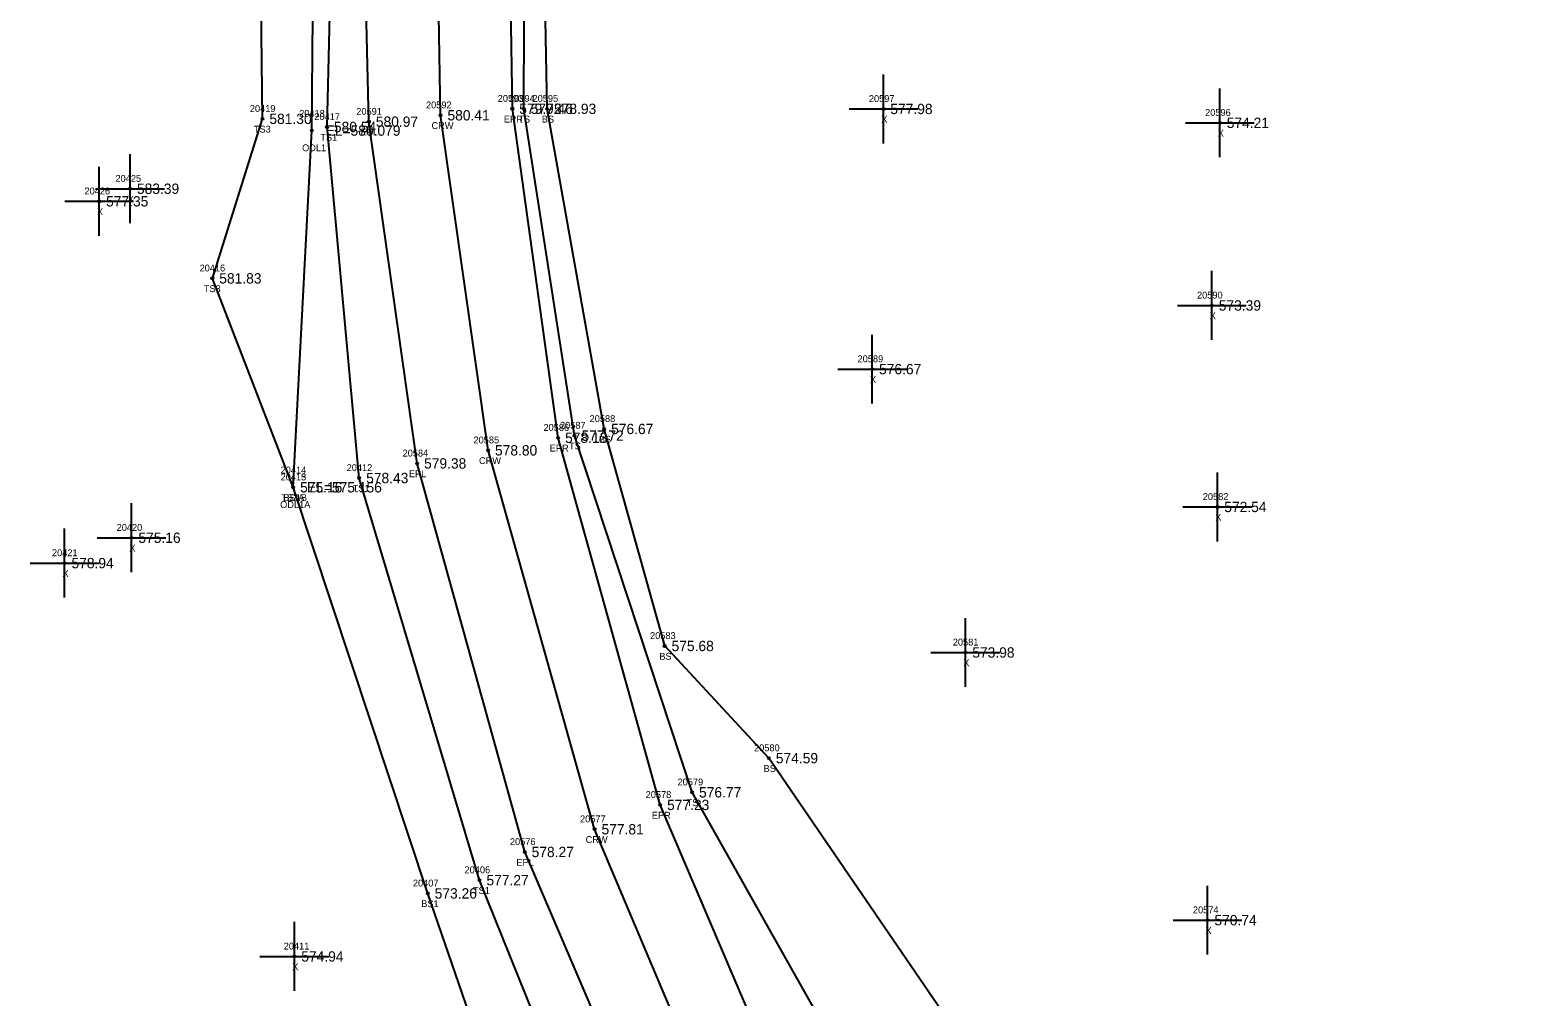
# Model space of a CAD drawing. Extents: x 1695443 to 1696344, y 1087542 to 1090645.
# Drawn here: x 1695658.7 to 1695877.6, y 1089254.7 to 1089395 of the extents above; entities that cross this region are included whole.
import ezdxf

# ---------------------------------------------------------------- set-up
doc = ezdxf.new("R2010")
doc.units = 0
for name, color, linetype in [('RD_DTM_BkLn1', 7, 'Continuous'), ('RD_DTM_BkLn2', 7, 'Continuous'), ('RD_DTM_BkLn_txCode', 7, 'Continuous'), ('RD_EX_H2O', 7, 'Continuous'), ('RD_EX_H2O_txCode', 7, 'Continuous'), ('RD_EX_Misc', 7, 'Continuous'), ('RD_EX_Misc_txCode', 7, 'Continuous'), ('RD_EX_Road', 7, 'Continuous'), ('RD_EX_Road_txCode', 7, 'Continuous'), ('RD_EX_TX_H2O_ELEV', 7, 'Continuous'), ('RD_EX_TX_Misc_ELEV', 7, 'Continuous'), ('RD_EX_TX_Road_ELEV', 7, 'Continuous'), ('RD_HC_Survey_ELEV', 7, 'Continuous'), ('RD_HC_Survey_txCode', 7, 'Continuous'), ('RD_SMD_Locator', 7, 'Continuous')]:
    doc.layers.add(name, color=color, linetype=linetype)

msp = doc.modelspace()

# ---------------------------------------------------------------- linework, layer by layer
at = {"layer": 'RD_DTM_BkLn1'}
msp.add_lwpolyline([(1695813.78, 1089148.1), (1695785.55, 1089189.03), (1695758.89, 1089235.87), (1695740.64, 1089279.02), (1695725.17, 1089334.02), (1695718.27, 1089382.65), (1695717.41, 1089435.13), (1695722.03, 1089482.62), (1695732.64, 1089534.75), (1695759.85, 1089631.43), (1695787.11, 1089727.89), (1695798.89, 1089774.41), (1695810.31, 1089824.5), (1695818.49, 1089870.61), (1695825.85, 1089922.33), (1695831.69, 1089976.57), (1695835.49, 1090019.27), (1695844.06, 1090117.91), (1695852.56, 1090215.73), (1695861.78, 1090313.02), (1695870.8, 1090411.68), (1695879.44, 1090510.15), (1695888.04, 1090606.94)], dxfattribs=at)
at = {"layer": 'RD_DTM_BkLn2'}
for points in [[(1695696.87, 1089328.65), (1695685.13, 1089358.98), (1695692.41, 1089382.13), (1695691.76, 1089435.56), (1695699.73, 1089488.72), (1695712.17, 1089543.62), (1695742.06, 1089638.06), (1695765.36, 1089733.76), (1695777.86, 1089780.36), (1695790.39, 1089828.61), (1695799.49, 1089874.59), (1695809.45, 1089923.14)], [(1695802.49, 1089139.56), (1695797.31, 1089139.87), (1695796.55, 1089145.92), (1695767.85, 1089172.77), (1695752.08, 1089198.99), (1695743.04, 1089224.25), (1695723.93, 1089271.63), (1695706.46, 1089330), (1695701.78, 1089380.95), (1695703.12, 1089435.75), (1695708.88, 1089486.48), (1695720.72, 1089539.1), (1695747.1, 1089636.56), (1695773.41, 1089730.59), (1695786.04, 1089777.66), (1695796.55, 1089826.24), (1695804.53, 1089873.75), (1695809.45, 1089923.14)], [(1695824.1, 1089156.08), (1695822.08, 1089163.12), (1695799.61, 1089199.21), (1695776.92, 1089245.16), (1695754.8, 1089284.38), (1695737.73, 1089336.15), (1695730.34, 1089383.59), (1695730.57, 1089435.13), (1695734.2, 1089480.03), (1695745.77, 1089531.16), (1695772.55, 1089627.13), (1695801.84, 1089724.13), (1695813.32, 1089771.8), (1695823.97, 1089812.55), (1695828.38, 1089814.06), (1695832.18, 1089812.32)], [(1695806.13, 1089128.88), (1695831.97, 1089151.08), (1695836.66, 1089166.87), (1695814.23, 1089210.18), (1695792.32, 1089250.79), (1695765.95, 1089289.34), (1695750.81, 1089305.62), (1695742.03, 1089337.12), (1695733.74, 1089383.59), (1695733.01, 1089422.34)], [(1695806.13, 1089128.88), (1695794.16, 1089128.75), (1695783.95, 1089141.34), (1695746.77, 1089175.62), (1695732.9, 1089221.78), (1695716.41, 1089269.71), (1695696.87, 1089328.65)]]:
    msp.add_lwpolyline(points, dxfattribs=at)
at = {"layer": 'RD_EX_H2O'}
msp.add_lwpolyline([(1695696.87, 1089328.65), (1695699.57, 1089380.43), (1695700.06, 1089435.96), (1695707.01, 1089487.43), (1695718.96, 1089539.87), (1695744.93, 1089637.33), (1695772.06, 1089731.31), (1695783.6, 1089778.47), (1695794.38, 1089827.05), (1695802.7, 1089874.04), (1695809.45, 1089923.14)], dxfattribs=at)
at = {"layer": 'RD_EX_Misc'}
for p, q in [((1695782.58, 1089378.57), (1695782.58, 1089388.57)), ((1695831.43, 1089376.55), (1695831.43, 1089386.55)), ((1695777.58, 1089383.57), (1695787.58, 1089383.57)), ((1695826.43, 1089381.55), (1695836.43, 1089381.55)), ((1695673.18, 1089366.99), (1695673.18, 1089376.99)), ((1695668.7, 1089365.16), (1695668.7, 1089375.16)), ((1695668.18, 1089371.99), (1695678.18, 1089371.99)), ((1695663.7, 1089370.16), (1695673.7, 1089370.16)), ((1695830.27, 1089350.05), (1695830.27, 1089360.05)), ((1695825.27, 1089355.05), (1695835.27, 1089355.05)), ((1695780.94, 1089340.8), (1695780.94, 1089350.8)), ((1695775.94, 1089345.8), (1695785.94, 1089345.8)), ((1695831.07, 1089320.8), (1695831.07, 1089330.8)), ((1695673.39, 1089316.33), (1695673.39, 1089326.33)), ((1695826.07, 1089325.8), (1695836.07, 1089325.8)), ((1695663.67, 1089312.65), (1695663.67, 1089322.65)), ((1695668.39, 1089321.33), (1695678.39, 1089321.33)), ((1695658.67, 1089317.65), (1695668.67, 1089317.65)), ((1695794.48, 1089299.68), (1695794.48, 1089309.68)), ((1695789.48, 1089304.68), (1695799.48, 1089304.68)), ((1695829.64, 1089260.82), (1695829.64, 1089270.82)), ((1695697.04, 1089255.56), (1695697.04, 1089265.56)), ((1695824.64, 1089265.82), (1695834.64, 1089265.82)), ((1695692.04, 1089260.56), (1695702.04, 1089260.56))]:
    msp.add_line(p, q, dxfattribs=at)
at = {"layer": 'RD_EX_Road'}
for points in [[(1695813.78, 1089148.1), (1695805.56, 1089142.08), (1695776.44, 1089183.94), (1695749.27, 1089231.88), (1695730.49, 1089275.72), (1695714.87, 1089332.12), (1695707.87, 1089381.72), (1695706.58, 1089435.34), (1695711.58, 1089484.26), (1695722.15, 1089537.59), (1695749.04, 1089634.88), (1695776.11, 1089730.43), (1695788.13, 1089777.42), (1695798.89, 1089826.76), (1695807.1, 1089870.03), (1695814.71, 1089923.3), (1695820.51, 1089978.16), (1695824.04, 1090019.79), (1695832.76, 1090119.06), (1695841.25, 1090216.76), (1695850.36, 1090314.41), (1695859.24, 1090411.82), (1695868.09, 1090511.63), (1695876.75, 1090608.38)], [(1695813.78, 1089148.1), (1695821.41, 1089154.05), (1695793.74, 1089194.54), (1695767.99, 1089240.85), (1695750.16, 1089282.55), (1695735.35, 1089335.84), (1695728.69, 1089383.6), (1695727.9, 1089434.83)]]:
    msp.add_lwpolyline(points, dxfattribs=at)
at = {"layer": 'RD_SMD_Locator'}
for centre in [(1695718.27, 1089382.65), (1695728.69, 1089383.6), (1695730.34, 1089383.59), (1695733.74, 1089383.59), (1695782.58, 1089383.57), (1695692.41, 1089382.13), (1695699.57, 1089380.43), (1695701.78, 1089380.95), (1695707.87, 1089381.72), (1695831.43, 1089381.55), (1695673.18, 1089371.99), (1695668.7, 1089370.16), (1695685.13, 1089358.98), (1695830.27, 1089355.05), (1695780.94, 1089345.8), (1695742.03, 1089337.12), (1695725.17, 1089334.02), (1695735.35, 1089335.84), (1695737.73, 1089336.15), (1695714.87, 1089332.12), (1695706.46, 1089330), (1695696.87, 1089328.65), (1695696.87, 1089328.65), (1695696.87, 1089328.65), (1695831.07, 1089325.8), (1695673.39, 1089321.33), (1695663.67, 1089317.65), (1695750.81, 1089305.62), (1695794.48, 1089304.68), (1695765.95, 1089289.34), (1695754.8, 1089284.38), (1695750.16, 1089282.55), (1695740.64, 1089279.02), (1695730.49, 1089275.72), (1695723.93, 1089271.63), (1695716.41, 1089269.71), (1695829.64, 1089265.82), (1695697.04, 1089260.56)]:
    msp.add_circle(centre, 0.15, dxfattribs=at)

# ---------------------------------------------------------------- texts
at = {"layer": 'RD_DTM_BkLn_txCode'}
for s, p in [('20594', (1695728.22, 1089384.59)), ('20595', (1695731.62, 1089384.59)), ('20419', (1695690.57, 1089383.13)), ('20417', (1695699.94, 1089381.95)), ('TS', (1695729.55, 1089381.59)), ('BS', (1695732.96, 1089381.59)), ('TS3', (1695691.16, 1089380.13)), ('TS1', (1695700.81, 1089378.95)), ('20416', (1695683.27, 1089359.98)), ('TS3', (1695683.89, 1089356.98)), ('20588', (1695739.91, 1089338.12)), ('20587', (1695735.61, 1089337.15)), ('TS', (1695736.93, 1089334.15)), ('BS', (1695741.25, 1089335.12)), ('20412', (1695704.63, 1089331)), ('20413', (1695695.04, 1089329.65)), ('20415', (1695695.04, 1089329.65)), ('TS3A', (1695695.14, 1089326.65)), ('BS1B', (1695695.45, 1089326.65)), ('TS1', (1695705.5, 1089328)), ('20583', (1695748.69, 1089306.62)), ('BS', (1695750.03, 1089303.62)), ('20580', (1695763.79, 1089290.34)), ('BS', (1695765.17, 1089287.34)), ('20579', (1695752.68, 1089285.38)), ('TS', (1695754, 1089282.38)), ('20406', (1695721.75, 1089272.63)), ('20407', (1695714.25, 1089270.71)), ('BS1', (1695715.46, 1089267.71)), ('TS1', (1695722.97, 1089269.63))]:
    msp.add_text(s, height=1, dxfattribs=at).set_placement(p)
at = {"layer": 'RD_EX_H2O_txCode'}
for s, p in [('20418', (1695697.74, 1089382.43)), ('ODL1', (1695698.16, 1089377.43)), ('20414', (1695695.04, 1089330.65)), ('ODL1A', (1695694.97, 1089325.65))]:
    msp.add_text(s, height=1, dxfattribs=at).set_placement(p)
at = {"layer": 'RD_EX_Misc_txCode'}
for s, p in [('20597', (1695780.46, 1089384.57)), ('X', (1695782.26, 1089381.57)), ('20596', (1695829.29, 1089382.55)), ('X', (1695831.12, 1089379.55)), ('20425', (1695671.06, 1089372.99)), ('20426', (1695666.56, 1089371.16)), ('X', (1695672.86, 1089369.99)), ('X', (1695668.38, 1089368.16)), ('20590', (1695828.11, 1089356.05)), ('X', (1695829.95, 1089353.05)), ('20589', (1695778.82, 1089346.8)), ('X', (1695780.62, 1089343.8)), ('20582', (1695828.95, 1089326.8)), ('20420', (1695671.23, 1089322.33)), ('X', (1695830.76, 1089323.8)), ('20421', (1695661.84, 1089318.65)), ('X', (1695673.07, 1089319.33)), ('X', (1695663.36, 1089315.65)), ('20581', (1695792.65, 1089305.68)), ('X', (1695794.17, 1089302.68)), ('20574', (1695827.52, 1089266.82)), ('X', (1695829.33, 1089263.82)), ('20411', (1695695.49, 1089261.56)), ('X', (1695696.73, 1089258.56))]:
    msp.add_text(s, height=1, dxfattribs=at).set_placement(p)
at = {"layer": 'RD_EX_Road_txCode'}
for s, p in [('20593', (1695726.57, 1089384.6)), ('20591', (1695706.03, 1089382.72)), ('EPR', (1695727.46, 1089381.6)), ('EPL', (1695706.66, 1089379.72)), ('20586', (1695733.21, 1089336.84)), ('20584', (1695712.75, 1089333.12)), ('EPR', (1695734.12, 1089333.84)), ('EPL', (1695713.67, 1089330.12)), ('20578', (1695748.05, 1089283.55)), ('EPR', (1695748.94, 1089280.55)), ('20576', (1695728.34, 1089276.72)), ('EPL', (1695729.28, 1089273.72))]:
    msp.add_text(s, height=1, dxfattribs=at).set_placement(p)
at = {"layer": 'RD_EX_TX_H2O_ELEV'}
for s, p in [('EL=580.079', (1695701.57, 1089379.68)), ('EL=575.156', (1695698.87, 1089327.9))]:
    msp.add_text(s, height=1.5, dxfattribs=at).set_placement(p)
at = {"layer": 'RD_EX_TX_Misc_ELEV'}
for s, p in [('581.30', (1695693.41, 1089381.38)), ('579.46', (1695731.34, 1089382.84)), ('578.93', (1695734.74, 1089382.84)), ('577.98', (1695783.58, 1089382.82)), ('574.21', (1695832.43, 1089380.8)), ('580.54', (1695702.78, 1089380.2)), ('583.39', (1695674.18, 1089371.24)), ('577.35', (1695669.7, 1089369.41)), ('581.83', (1695686.13, 1089358.23)), ('573.39', (1695831.27, 1089354.3)), ('576.67', (1695781.94, 1089345.05)), ('577.72', (1695738.73, 1089335.4)), ('576.67', (1695743.03, 1089336.37)), ('578.43', (1695707.46, 1089329.25)), ('575.16', (1695697.87, 1089327.9)), ('575.16', (1695697.87, 1089327.9)), ('572.54', (1695832.07, 1089325.05)), ('575.16', (1695674.39, 1089320.58)), ('578.94', (1695664.67, 1089316.9)), ('575.68', (1695751.81, 1089304.87)), ('573.98', (1695795.48, 1089303.93)), ('574.59', (1695766.95, 1089288.59)), ('576.77', (1695755.8, 1089283.63)), ('577.27', (1695724.93, 1089270.88)), ('573.26', (1695717.41, 1089268.96)), ('570.74', (1695830.64, 1089265.07)), ('574.94', (1695698.04, 1089259.81))]:
    msp.add_text(s, height=1.5, dxfattribs=at).set_placement(p)
at = {"layer": 'RD_EX_TX_Road_ELEV'}
for s, p in [('580.97', (1695708.87, 1089380.97)), ('579.72', (1695729.69, 1089382.85)), ('578.13', (1695736.35, 1089335.09)), ('579.38', (1695715.87, 1089331.37)), ('577.23', (1695751.16, 1089281.8)), ('578.27', (1695731.49, 1089274.97))]:
    msp.add_text(s, height=1.5, dxfattribs=at).set_placement(p)
at = {"layer": 'RD_HC_Survey_ELEV'}
for s, p in [('580.41', (1695719.27, 1089381.9)), ('578.80', (1695726.17, 1089333.27)), ('577.81', (1695741.64, 1089278.27))]:
    msp.add_text(s, height=1.5, dxfattribs=at).set_placement(p)
at = {"layer": 'RD_HC_Survey_txCode'}
for s, p in [('20592', (1695716.15, 1089383.65)), ('CRW', (1695716.95, 1089380.65)), ('20585', (1695723.05, 1089335.02)), ('CRW', (1695723.85, 1089332.02)), ('20577', (1695738.52, 1089280.02)), ('CRW', (1695739.33, 1089277.02))]:
    msp.add_text(s, height=1, dxfattribs=at).set_placement(p)

doc.saveas('drawing.dxf')
